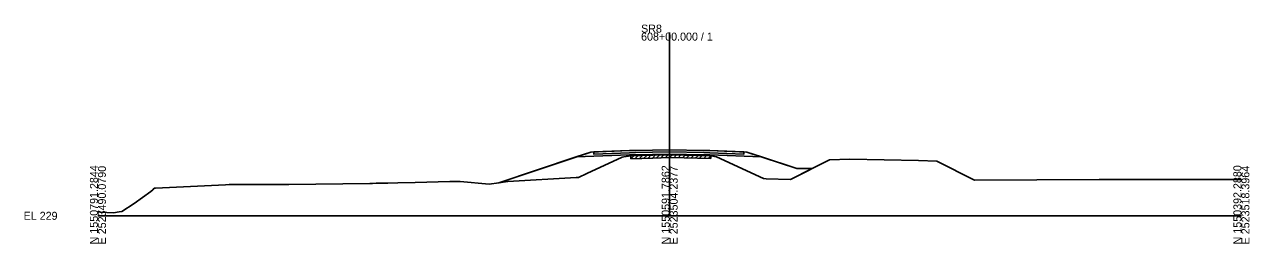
# Model space of a CAD drawing. Extents: x -26 to 2803, y -10 to 19537.
# Drawn here: x -25.7 to 402.8, y 13990.3 to 14066.9 of the extents above; entities that cross this region are included whole.
import ezdxf

# ---------------------------------------------------------------- set-up
doc = ezdxf.new("R2010")
doc.units = 0
for name, color, linetype in [('1', 7, 'Continuous'), ('Draft_XS_Grid', 7, 'Continuous'), ('Draft_XS_Text', 7, 'Continuous'), ('DTM_P_SUBGRADE_1', 7, 'Continuous'), ('DTM_X_GROUND', 7, 'Continuous'), ('SLOPE_STAKES_FILL', 7, 'Continuous'), ('XS_P_ASPHALT', 7, 'Continuous'), ('XS_P_SHOULDER', 7, 'Continuous')]:
    doc.layers.add(name, color=color, linetype=linetype)

msp = doc.modelspace()

# ---------------------------------------------------------------- linework, layer by layer
at = {"layer": '1'}
for p, q in [((200, 14000), (200, 14064.1)), ((0, 14000), (200, 14000)), ((200, 14000), (400, 14000))]:
    msp.add_line(p, q, dxfattribs=at)
at = {"layer": 'Draft_XS_Grid'}
for p, q in [((186.44, 14019.98), (187.47, 14021.01)), ((186.44, 14019.98), (186.44, 14020.98)), ((186.44, 14019.98), (194.17, 14020.19)), ((187.94, 14020.02), (188.97, 14021.05)), ((189.44, 14020.06), (190.47, 14021.09)), ((190.94, 14020.11), (191.97, 14021.13)), ((192.44, 14020.15), (193.47, 14021.18)), ((193.94, 14020.19), (194.97, 14021.22)), ((194.17, 14020.19), (200, 14020.35)), ((195.44, 14020.23), (196.47, 14021.26)), ((196.94, 14020.27), (197.97, 14021.3)), ((198.44, 14020.31), (199.47, 14021.34)), ((199.94, 14020.35), (200.94, 14021.35)), ((200, 14020.35), (200.43, 14020.37)), ((200.43, 14020.37), (214.44, 14020.01)), ((201.44, 14020.34), (202.42, 14021.32)), ((202.94, 14020.3), (203.92, 14021.28)), ((204.44, 14020.27), (205.42, 14021.24)), ((205.94, 14020.23), (206.92, 14021.2)), ((207.44, 14020.19), (208.42, 14021.17)), ((208.94, 14020.15), (209.92, 14021.13)), ((210.44, 14020.11), (211.42, 14021.09)), ((211.94, 14020.08), (212.92, 14021.05)), ((213.44, 14020.04), (214.42, 14021.01)), ((214.44, 14021.01), (214.44, 14020.01))]:
    msp.add_line(p, q, dxfattribs=at)
at = {"layer": 'Draft_XS_Text'}
for p, q in [((242.24, 14012.72), (255.91, 14019.54)), ((255.91, 14019.54), (263, 14019.82)), ((263, 14019.82), (275, 14019.58)), ((275, 14019.58), (287, 14019.34)), ((287, 14019.34), (293.47, 14019.08)), ((293.47, 14019.08), (306.67, 14012.5))]:
    msp.add_line(p, q, dxfattribs=at)
for points in [[(0, 14001.57), (0.84, 14001.26), (3.07, 14001.15), (5.47, 14001.04), (7.41, 14001.35), (8.37, 14001.49), (12.64, 14004.25), (18.54, 14008.53), (19.2, 14009.07), (19.71, 14009.67), (20.12, 14009.67), (44.62, 14010.88), (45.91, 14010.91), (47.76, 14010.95), (66.81, 14010.99), (95.1, 14011.32), (96.08, 14011.34), (97.34, 14011.37), (99.02, 14011.41), (101.39, 14011.47), (104.96, 14011.55), (110.96, 14011.7), (123.15, 14011.99), (125.59, 14012.05), (126.68, 14012.06), (136.86, 14011.11), (140.2, 14011.58), (143.42, 14012.01), (167.25, 14013.38), (168.06, 14013.43), (171.05, 14014.82), (183.37, 14020.54), (183.94, 14020.62), (186.44, 14020.98), (194.17, 14021.19), (200, 14021.35), (200.43, 14021.37), (214.44, 14021.01), (216.39, 14020.58), (232.87, 14013.01), (233.73, 14012.98), (242.24, 14012.72)], [(306.67, 14012.5), (350.23, 14012.7), (360.27, 14012.69), (378.87, 14012.68), (400, 14012.67)]]:
    msp.add_lwpolyline(points, dxfattribs=at)
at = {"layer": 'DTM_P_SUBGRADE_1'}
for p, q in [((188, 14021.37), (200, 14021.61)), ((200, 14021.61), (212, 14021.37)), ((186, 14021.33), (167.34, 14020.58)), ((188, 14021.37), (186, 14021.33)), ((212, 14021.37), (214, 14021.33)), ((214, 14021.33), (232.16, 14020.6))]:
    msp.add_line(p, q, dxfattribs=at)
at = {"layer": 'DTM_X_GROUND'}
for p, q in [((172.47, 14022.29), (140.27, 14011.59)), ((186, 14022.83), (172.47, 14022.29)), ((188, 14022.87), (186, 14022.83)), ((188, 14022.87), (200, 14023.11)), ((200, 14023.11), (212, 14022.87)), ((212, 14022.87), (214, 14022.83)), ((214, 14022.83), (227.04, 14022.31)), ((227.04, 14022.31), (244.47, 14016.5)), ((244.47, 14016.5), (249.82, 14016.5))]:
    msp.add_line(p, q, dxfattribs=at)
at = {"layer": 'SLOPE_STAKES_FILL'}
for p, q in [((140.27, 14011.59), (172.47, 14022.29)), ((172.47, 14022.29), (186, 14022.83)), ((186, 14022.83), (188, 14022.87)), ((188, 14022.87), (200, 14023.11)), ((200, 14023.11), (212, 14022.87)), ((212, 14022.87), (214, 14022.83)), ((214, 14022.83), (227.04, 14022.31)), ((227.04, 14022.31), (244.47, 14016.5)), ((249.82, 14016.5), (255.91, 14019.54)), ((255.91, 14019.54), (263, 14019.82)), ((263, 14019.82), (275, 14019.58)), ((275, 14019.58), (287, 14019.34)), ((287, 14019.34), (293.47, 14019.08)), ((293.47, 14019.08), (306.67, 14012.5)), ((244.47, 14016.5), (249.82, 14016.5))]:
    msp.add_line(p, q, dxfattribs=at)
for points in [[(0, 14001.57), (0.84, 14001.26), (3.07, 14001.15), (5.47, 14001.04), (7.41, 14001.35), (8.37, 14001.49), (12.64, 14004.25), (18.54, 14008.53), (19.2, 14009.07), (19.71, 14009.67), (20.12, 14009.67), (44.62, 14010.88), (45.91, 14010.91), (47.76, 14010.95), (66.81, 14010.99), (95.1, 14011.32), (96.08, 14011.34), (97.34, 14011.37), (99.02, 14011.41), (101.39, 14011.47), (104.96, 14011.55), (110.96, 14011.7), (123.15, 14011.99), (125.59, 14012.05), (126.68, 14012.06), (136.86, 14011.11), (140.2, 14011.58), (140.27, 14011.59)], [(306.67, 14012.5), (350.23, 14012.7), (360.27, 14012.69), (378.87, 14012.68), (400, 14012.67)]]:
    msp.add_lwpolyline(points, dxfattribs=at)
at = {"layer": 'XS_P_ASPHALT'}
for p, q in [((173.47, 14021.58), (173.47, 14022.33)), ((186, 14022.08), (173.47, 14021.58)), ((188, 14022.12), (186, 14022.08)), ((188, 14022.12), (200, 14022.36)), ((200, 14022.36), (212, 14022.12)), ((212, 14022.12), (214, 14022.08)), ((214, 14022.08), (225.98, 14021.6)), ((225.98, 14021.6), (225.98, 14022.35))]:
    msp.add_line(p, q, dxfattribs=at)
at = {"layer": 'XS_P_SHOULDER'}
for points in [[(232.16, 14020.6), (244.47, 14016.5), (249.82, 14016.5), (242.24, 14012.72), (233.73, 14012.98), (232.87, 14013.01), (216.39, 14020.58), (214.44, 14021.01), (200.43, 14021.37), (200, 14021.35), (194.17, 14021.19), (186.44, 14020.98), (183.94, 14020.62), (183.37, 14020.54), (171.05, 14014.82), (168.06, 14013.43), (167.25, 14013.38), (143.42, 14012.01), (140.27, 14011.59), (167.34, 14020.58), (186, 14021.33), (188, 14021.37), (200, 14021.61), (212, 14021.37), (214, 14021.33)], [(173.47, 14022.33), (172.47, 14022.29), (167.34, 14020.58), (186, 14021.33), (188, 14021.37), (200, 14021.61), (212, 14021.37), (214, 14021.33), (232.16, 14020.6), (227.04, 14022.31), (225.98, 14022.35), (225.98, 14021.6), (214, 14022.08), (212, 14022.12), (200, 14022.36), (188, 14022.12), (186, 14022.08), (173.47, 14021.58)], [(200, 14023.11), (212, 14022.87), (214, 14022.83), (225.98, 14022.35), (225.98, 14021.6), (214, 14022.08), (212, 14022.12), (200, 14022.36), (188, 14022.12), (186, 14022.08), (173.47, 14021.58), (173.47, 14022.33), (186, 14022.83), (188, 14022.87)]]:
    msp.add_lwpolyline(points, close=True, dxfattribs=at)

# ---------------------------------------------------------------- texts
at = {"layer": '1'}
for s, p in [('SR8', (190, 14064.1)), ('608+00.000 / 1', (190, 14061.3)), ('EL 229', (-26, 13998.6))]:
    msp.add_text(s, height=2.8, dxfattribs=at).set_placement(p)
for s, p in [('N 1550791.2844', (0, 13990)), ('E 2523490.0790', (2.8, 13990)), ('N 1550591.7862', (200, 13990)), ('N 1550392.2880', (400, 13990)), ('E 2523518.3964', (402.8, 13990)), ('E 2523504.2377', (202.8, 13990))]:
    msp.add_text(s, height=2.8, rotation=90, dxfattribs=at).set_placement(p)

doc.saveas('drawing.dxf')
